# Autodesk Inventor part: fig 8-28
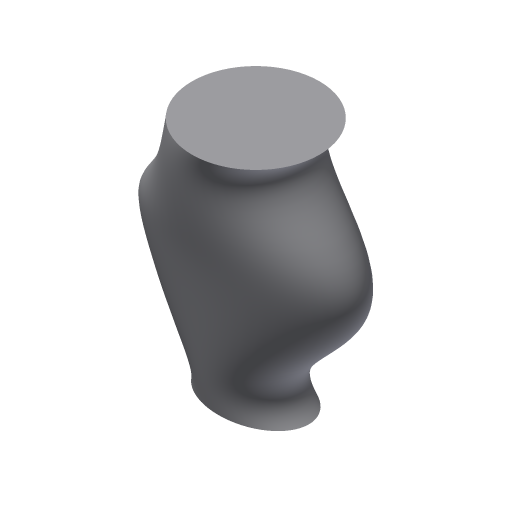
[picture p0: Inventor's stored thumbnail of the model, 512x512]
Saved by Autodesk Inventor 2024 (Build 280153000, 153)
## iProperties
Shininess: 64.0
Length Units: 11269
Angle Units: 11279
Time Units: 11290
Mass Units: 11283
Length Display Precision: 3
Angle Display Precision: 2
Compacted: True
Part Number: fig 8-28
Document SubType Name: Modeling
Created: 2002-12
Designer: deepak
Density: 1 g/cm^3
Material: Generic
Appearance: Default
Density: 0.0
Volumn: 0.0
Area: 0.0
PropertySet Name: Model Information
Control State: 0
Master: False
Checked Out: False
Author: deepak
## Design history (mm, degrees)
sketch "Sketch1"
  geometry: 2 further points; 1 other entity
  constraints: 1 coincident, 3 other
workplane "Work Plane1"
workplane "Work Plane2"
sketch "Sketch3"
  geometry: C1 r 60 at (0, 0); 1 further point
  constraints: 1 centre point, 1 coincident, 1 other
sketch "Sketch4"
  geometry: 8 further points
  constraints: 8 other
sketch "Sketch5"
  geometry: 6 further points
  constraints: 6 other
sketch "Sketch6"
  geometry: 6 further points
  constraints: 6 other
  dimensions: "d20" = 35 distance of point (0, 0) point (-35, 0); "d21" = 0 vertical distance of point (0, 0) point (-35, 0); "d22" = 225 vertical distance of point (0, 0) point (-60, 225); "d23" = 60 horizontal distance of point (0, 0) point (-60, 225); "d24" = 100 horizontal distance of point (0, 0) point (-100, 125); "d25" = 125 vertical distance of point (0, 0) point (-100, 125)
loft "Loft5" dims "d54" = 0, "d55" = 90 deg, "d56" = 0, "d57" = 90 deg, "d58" = 0, "d59" = 90 deg, "d60" = 0, "d61" = 90 deg
body "Solid2"
other parameters: "d5" = 125
